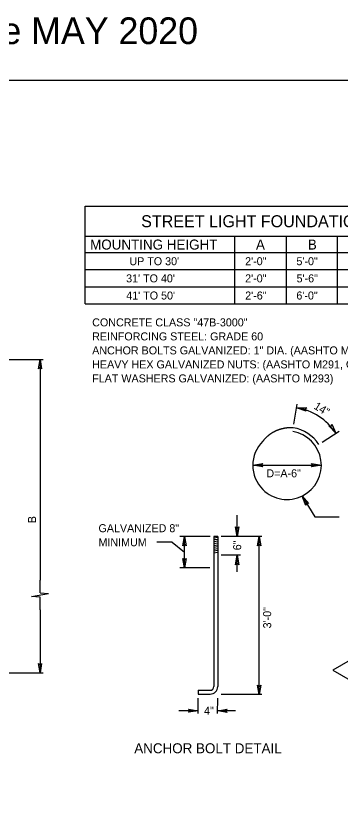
# Model space of a CAD drawing. Extents: x 99836 to 115004, y 99786 to 102182.
# Drawn here: x 111008 to 111494, y 100984 to 102182 of the extents above; entities that cross this region are included whole.
import ezdxf

# ---------------------------------------------------------------- set-up
doc = ezdxf.new("R2010")
doc.units = 0
for name, color, linetype in [('Border Line', 7, 'Continuous'), ('Border Organizer Shape', 7, 'Continuous'), ('Default', 7, 'Continuous'), ('Notes General Notes', 7, 'Continuous')]:
    doc.layers.add(name, color=color, linetype=linetype)

msp = doc.modelspace()

# ---------------------------------------------------------------- linework, layer by layer
at = {"layer": 'Border Organizer Shape'}
for p, q in [((111111.4, 101896.9), (111728.2, 101896.9)), ((111111.4, 101750.5), (111111.4, 101896.9)), ((111111.4, 101851.9), (111728.2, 101851.9)), ((111335.4, 101750.5), (111335.4, 101851.9)), ((111412.5, 101750.5), (111412.5, 101851.9)), ((111489.2, 101750.5), (111489.2, 101851.9)), ((111111.4, 101827.5), (111728.2, 101827.5)), ((111111.4, 101801.9), (111728.2, 101801.9)), ((111111.4, 101776.2), (111728.2, 101776.2)), ((111111.4, 101750.5), (111728.2, 101750.5)), ((110940.4, 101667.2), (111048.3, 101667.2)), ((111043.7, 101667.2), (111043.7, 101336.1)), ((111423.8, 101570.3), (111428.9, 101600.3)), ((111466.1, 101543.1), (111491.4, 101559.8)), ((111362.3, 101508.4), (111464.9, 101508.4)), ((111338.9, 101401.9), (111338.9, 101433.7)), ((111298.5, 101401.9), (111252.8, 101401.9)), ((111260, 101354.6), (111260, 101401.9)), ((111304, 101401.9), (111304, 101383)), ((111309.7, 101401.9), (111304, 101401.9)), ((111309.7, 101400.1), (111304, 101399.2)), ((111309.7, 101397.4), (111304, 101396.5)), ((111309.7, 101401.9), (111309.7, 101383)), ((111375.8, 101401.8), (111314.9, 101401.9)), ((111371.7, 101164.6), (111371.9, 101401.8)), ((111241.7, 101393.1), (111218.4, 101393.1)), ((111241.7, 101393.1), (111259.9, 101378.2)), ((111309.6, 101386.1), (111303.9, 101385.2)), ((111309.7, 101394.6), (111304, 101393.7)), ((111309.6, 101391.8), (111304, 101390.9)), ((111309.6, 101388.8), (111304, 101387.9)), ((111309.6, 101383.3), (111304, 101382.4)), ((111304, 101383), (111304, 101176.7)), ((111309.5, 101380.5), (111304, 101379.6)), ((111309.5, 101377.5), (111304, 101376.6)), ((111309.7, 101383), (111309.7, 101176.7)), ((111344, 101373.5), (111314.8, 101373.5)), ((111338.8, 101348.5), (111338.9, 101373.5)), ((111297.8, 101354.6), (111252.8, 101354.6)), ((111043.7, 101317.2), (111043.7, 101336.1)), ((111030.9, 101311.6), (111056.6, 101316.1)), ((111043.7, 101317.2), (111056.6, 101316.1)), ((111043.7, 101310.6), (111030.9, 101311.6)), ((111043.7, 101291.6), (111043.7, 101310.6)), ((111043.7, 101291.6), (111043.7, 101197)), ((110778.5, 101197), (111048.3, 101197)), ((111280.3, 101171.1), (111298.3, 101171.1)), ((111280.3, 101171.1), (111280.3, 101165.4)), ((111280.3, 101165.4), (111298.3, 101165.4)), ((111280.3, 101136.3), (111280.3, 101159.2)), ((111309.6, 101136.2), (111309.7, 101159.2)), ((111375.7, 101164.6), (111314.7, 101164.7)), ((111280.3, 101140.5), (111251.4, 101140.5)), ((111336.3, 101140.4), (111309.7, 101140.4))]:
    msp.add_line(p, q, dxfattribs=at)
for points in [[(111041.4, 101653.1), (111043.7, 101667.2), (111046.1, 101653.1), (111043.7, 101655.3)], [(111442.2, 101589.7), (111427.9, 101594.6), (111443, 101594.7), (111440.3, 101592.6)], [(111480.4, 101570.3), (111486.5, 101556.6), (111476.3, 101567.6), (111479.7, 101567)], [(111377.1, 101505.9), (111362.3, 101508.4), (111377.1, 101510.9), (111374.8, 101508.4)], [(111450, 101510.9), (111464.9, 101508.4), (111450, 101505.9), (111452.4, 101508.4)], [(111441.7, 101448.3), (111436, 101462.3), (111445.9, 101451), (111442.6, 101451.6)], [(111341.3, 101416), (111338.9, 101401.9), (111336.5, 101416), (111338.9, 101413.7)], [(111257.6, 101387.8), (111260, 101401.9), (111262.4, 101387.8), (111260, 101390)], [(111369.4, 101387.7), (111371.9, 101401.8), (111374.2, 101387.7), (111371.8, 101390)], [(111336.5, 101359.4), (111338.9, 101373.5), (111341.2, 101359.4), (111338.8, 101361.6)], [(111262.4, 101368.7), (111260, 101354.6), (111257.6, 101368.7), (111260, 101366.5)], [(111046.1, 101211.2), (111043.7, 101197), (111041.4, 101211.2), (111043.7, 101208.9)], [(111374.1, 101178.7), (111371.7, 101164.6), (111369.3, 101178.8), (111371.7, 101176.5)], [(111266.2, 101142.9), (111280.3, 101140.5), (111266.2, 101138.1), (111268.5, 101140.5)], [(111323.8, 101138), (111309.7, 101140.4), (111323.8, 101142.8), (111321.5, 101140.4)]]:
    msp.add_lwpolyline(points, close=True, dxfattribs=at)
msp.add_lwpolyline([(111436, 101462.3), (111455.1, 101431.3), (111491.6, 101431.3)], dxfattribs=at)
for centre, radius, start, end in [((111413.6, 101508.4), 87.4, 33.427, 80.5536), ((111413.6, 101508.4), 57, 33.4279, 80.5568), ((111413.6, 101508.4), 51.3, 224.9925, 80.5568), ((111413.6, 101508.4), 51.3, 134.9925, 224.9925), ((111298.3, 101176.7), 5.68, 270, 360), ((111298.3, 101176.7), 11.4, 270, 360)]:
    msp.add_arc(centre, radius, start, end, dxfattribs=at)
msp.add_spline([(111422.9, 101564.7), (111422.1, 101564.7), (111421.4, 101564.8), (111420.6, 101564.8), (111419.7, 101564.8), (111419, 101564.8), (111418.2, 101564.7), (111417.4, 101564.7), (111416.5, 101564.7), (111415.8, 101564.6), (111415, 101564.5), (111414.2, 101564.5), (111413.4, 101564.4), (111412.6, 101564.3), (111411.8, 101564.2), (111411.1, 101564.1), (111410.3, 101564), (111409.5, 101563.9), (111408.7, 101563.7), (111407.9, 101563.5), (111407.2, 101563.3), (111406.3, 101563.1), (111405.6, 101563), (111404.9, 101562.8), (111404, 101562.5), (111403.3, 101562.3), (111402.5, 101562.1), (111401.8, 101561.9), (111401, 101561.6), (111400.3, 101561.3), (111399.5, 101561), (111398.8, 101560.7), (111398, 101560.4), (111397.3, 101560.1), (111396.6, 101559.8), (111395.8, 101559.4), (111395.1, 101559), (111394.5, 101558.7), (111393.7, 101558.3), (111393, 101557.9), (111392.4, 101557.6), (111391.6, 101557.2), (111390.9, 101556.7), (111390.3, 101556.4), (111389.6, 101555.9), (111389, 101555.5), (111388.3, 101555), (111387.6, 101554.6), (111387, 101554.1), (111386.4, 101553.6), (111385.7, 101553.1), (111385.2, 101552.6), (111384.5, 101552.1), (111383.9, 101551.6), (111383.3, 101551.1), (111382.7, 101550.5), (111382.2, 101550), (111381.6, 101549.5), (111381.1, 101548.9), (111380.4, 101548.3), (111379.9, 101547.7), (111379.4, 101547.2), (111378.9, 101546.5), (111378.3, 101545.9), (111377.8, 101545.3), (111377.3, 101544.7)], degree=3, dxfattribs=at)
at = {"layer": 'Default'}
msp.add_lwpolyline([(110176.3, 102085.7), (113376, 102085.7), (113376, 99886.1), (110176.3, 99886.1)], close=True, dxfattribs=at)
at = {"layer": 'Notes General Notes'}
msp.add_lwpolyline([(111482.2, 101201.3), (111543.7, 101165.8), (111543.7, 101183.6), (111614.6, 101183.6), (111614.6, 101219), (111543.7, 101219), (111543.7, 101236.8)], close=True, dxfattribs=at)

# ---------------------------------------------------------------- texts
at = {"layer": 'Border Line'}
msp.add_text('Approved Date MAY 2020', height=40, dxfattribs=at).set_placement((110658.8, 102140))
at = {"layer": 'Border Organizer Shape'}
for s, height, p in [('STREET LIGHT FOUNDATION DATA', 18, (111195.1, 101865.4)), ('MOUNTING HEIGHT', 15, (111118.7, 101831.9)), ('A', 15, (111367, 101831.9)), ('B', 15, (111444.7, 101831.9)), ("UP TO 30'", 12, (111177.5, 101808.4)), ('2\'-0"', 12, (111350.8, 101808.4)), ('5\'-0"', 12, (111427.6, 101808.4)), ("31' TO 40'", 12, (111172.6, 101782.7)), ('2\'-0"', 12, (111350.8, 101782.7)), ('5\'-6"', 12, (111427.8, 101782.7)), ("41' TO 50'", 12, (111172.8, 101757)), ('2\'-6"', 12, (111350.9, 101757)), ('6\'-0"', 12, (111427.5, 101757)), ('CONCRETE CLASS "47B-3000"', 12, (111121.8, 101716.7)), ('REINFORCING STEEL: GRADE 60', 12, (111121.8, 101695.7)), ('ANCHOR BOLTS GALVANIZED: 1" DIA. (AASHTO M314, GR.55)', 12, (111121.8, 101674.7)), ('HEAVY HEX GALVANIZED NUTS: (AASHTO M291, GR A)', 12, (111121.8, 101653.7)), ('FLAT WASHERS GALVANIZED: (AASHTO M293)', 12, (111121.8, 101632.7)), ('GALVANIZED 8"', 12, (111131.2, 101408.1)), ('MINIMUM ', 12, (111131.2, 101387.1)), ('4"', 12, (111289.3, 101134.5)), ('ANCHOR BOLT DETAIL', 15, (111184.8, 101076.6))]:
    msp.add_text(s, height=height, dxfattribs=at).set_placement(p)
for s, rotation, p in [('14"', 328.8322, (111452.5, 101594)), ('D=A-6"', 359.9925, (111382.6, 101490.4)), ('B', 90, (111037.7, 101421.6)), ('6"', 90, (111344.9, 101381)), ('3\'-0"', 90, (111389.8, 101263.9))]:
    msp.add_text(s, height=12, rotation=rotation, dxfattribs=at).set_placement(p)

doc.saveas('drawing.dxf')
